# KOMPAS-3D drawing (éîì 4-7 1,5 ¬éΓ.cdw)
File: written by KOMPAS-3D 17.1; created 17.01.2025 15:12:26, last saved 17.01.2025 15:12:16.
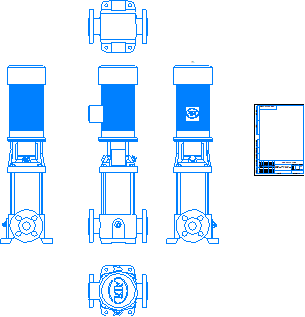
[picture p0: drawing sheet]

Sheet 1: A4, portrait

Title block, sheet 1: name: ВМН 4-7 1,5 кВт; designation: ВМН 4-7 1,5 кВт; sheets: 1; sheet format: A4; stored path: \\adlc.lan\data\АДЛ_ПКД\3D-модели\ADL production\Насосы ГРАНПАМП\Насосы ВМН\ВМН4\KOMPAS 2D\ВМН 4-7 1,5 кВт.cdw

Views: Проекционный вид 2, Проекционный вид 3, Проекционный вид 4, Проекционный вид 5
Referenced files in \\adlc.lan\data\АДЛ_ПКД\3D-модели\ADL production\Насосы ГРАНПАМП\Насосы ВМН\ВМН4\KOMPAS 3D\: ВМН 4-7 1,5 кВт.m3d
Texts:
  Andrey
  АДЛ
Dimensions and other numbers on the sheet: 1:1; 1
